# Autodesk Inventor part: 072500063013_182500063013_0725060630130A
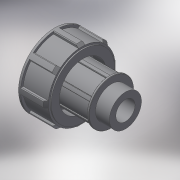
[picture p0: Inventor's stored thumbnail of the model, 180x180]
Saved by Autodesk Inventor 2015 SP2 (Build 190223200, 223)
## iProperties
Created: 2017-04
Part Number: 072500063013_182500063013_0725060630130A
Material: Generic
Description: PLASSON THREADED ADAPTOR 63-1.1/4"
Document SubType Name: Modeling
Designer: KIM
Density: 1 g/cm^3
Appearance: Default
Author: KIM
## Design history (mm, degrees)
derived "07250.ipt"
feature "Solid1::07250.ipt"
tag "TaggingFeature1"
body "Solid1"
other parameters: "d1" = 41.91, "d2" = 111, "d3" = 22, "d6" = 113, "d7" = 105.09, "d8" = 90.4, "d9" = 63, "d10" = 67.056, "d12" = 25.146, "d13" = 33.528, "d14" = 25.3, "d15" = 84.75, "d16" = 3.33, "d17" = 44.4, "d18" = 22, "d19" = 26.4, "d24" = 8.382, "d25" = 4.191, "d27" = 0, "d28" = 3.3528, "d31" = 0.8382, "d35" = 360 deg, "d41" = 29.337, "d56" = 66.15, "d57" = 6.3, "d58" = 3.15, "d60" = 0, "d61" = 0.4191, "d64" = 0.4191, "d68" = 360 deg, "d_" = 63, "R_" = 41.91, "E_" = 113, "H_" = 111, "l_2" = 22, "d55" = 63
